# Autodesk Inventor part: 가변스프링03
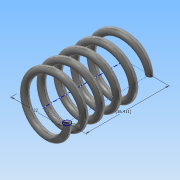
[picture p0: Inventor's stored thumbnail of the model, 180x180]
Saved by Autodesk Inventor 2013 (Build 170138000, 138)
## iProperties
Created: 2014-07
Part Number: 가변스프링03
Material: 강철, 탄소
Document SubType Name: Modeling
Designer: SEMTLE01_MAIN
Density: 7.87 g/cm^3
Mass: 18.8881 g
Surface Area: 32.5243 cm^2
Volume: 2.40001 cm^3
Author: SEMTLE01_MAIN
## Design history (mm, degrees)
sketch "스케치1"
  geometry: L1 (0, 0)-(11, 0); L2 (11, 0)-(11, 36.411); L3 (11, 36.411)-(0, 36.411); L4 (0, 36.411)-(0, 0); C1 r 1.5 at (11, 0)
  constraints: 8 end point, 2 parallel, 1 centre point, 1 coincident, 1 horizontal, 1 perpendicular
  dimensions: "d0" = 3 diameter of C1; "d2" = 22 diameter of L1.end L4; "d3" = 36.4112 distance of L1.end L2.end (derived)
feature "코일1" pitch "d4" = 10; turns "d6" = 5; dims "d5" = 36.4112 (= d3), "d7" = 0, angle "d8" = 90 deg, angle "d9" = 90 deg, "d10" = 0, "d11" = 0
sketch "스케치2"
  geometry: L1 (-12.5, 0)-(-9.5, 0) reference; 1 further point
  constraints: 1 horizontal alignment
extrude "돌출1" cut sketch "스케치2" stored distance "d12" = 10; taper "d13" = 0 deg
node "작업 평면1"
sketch "스케치3"
  geometry: L1 (1.5, 0)-(-1.5, 0) reference; 1 further point
  constraints: 1 horizontal alignment
extrude "돌출2" cut sketch "스케치3" stored distance "d15" = 10; taper "d16" = 0 deg
node "솔리드1"
node "절단 모서리 투영1"
node "절단 모서리 투영2"
other parameters: "d14" = 0
